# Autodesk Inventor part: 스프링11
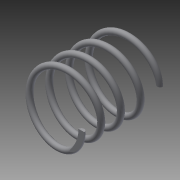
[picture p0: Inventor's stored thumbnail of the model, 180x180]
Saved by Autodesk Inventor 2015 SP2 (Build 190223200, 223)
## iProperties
Created: 2015-06
Part Number: 스프링11
Material: 일반
Document SubType Name: Modeling
Designer: AMC
Density: 1 g/cm^3
Appearance: 기본값
Mass: 0.349967 g
Surface Area: 9.47047 cm^2
Volume: 0.349967 cm^3
Author: AMC
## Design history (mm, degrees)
sketch "스케치1"
  geometry: L1 (0, 0)-(8, 0); L2 (0, 0)-(0, 14.102); C1 r 0.75 at (8, 0)
  constraints: 4 end point, 1 centre point, 1 coincident, 1 horizontal, 1 vertical
  dimensions: "d0" = 8 distance of L1.start L1.end; "d1" = 1.5 diameter of C1
feature "코일1" sketch "스케치1" pitch "d2" = 10; turns "d4" = 4; dims "d3" = 20.5 (= aa), "d5" = 0, angle "d6" = 90 deg, angle "d7" = 90 deg, "d8" = 0, "d9" = 0
sketch "스케치2"
  geometry: L1 (2.181, 0)-(-17.271, 0); L2 (-17.271, 0)-(-17.271, -4.707); L3 (-17.271, -4.707)-(2.181, -4.707); L4 (2.181, -4.707)-(2.181, 0); L5 (3.025, 20.5)-(-21.212, 20.5); L6 (-21.212, 20.5)-(-21.212, 25.441); L7 (-21.212, 25.441)-(3.025, 25.441); L8 (3.025, 25.441)-(3.025, 20.5); C1 r 0.75 at (0, 0) reference; C2 r 0.75 at (0, 20.5) reference; 8 further points
  constraints: 16 end point, 4 parallel, 2 horizontal, 2 perpendicular, 1 point on line, 7 other
  dimensions: "d10" = 20.5 distance between parallel lines of L1 L5 (= aa)
extrude "돌출1" cut sketch "스케치2" stored distance "d11" = 50; taper "d12" = 0 deg
node "솔리드1"
node "절단 모서리 투영1"
other parameters: "aa" = 20.5 [user parameter; used in 2 equation terms]
